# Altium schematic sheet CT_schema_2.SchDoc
size 283 x 147 mm
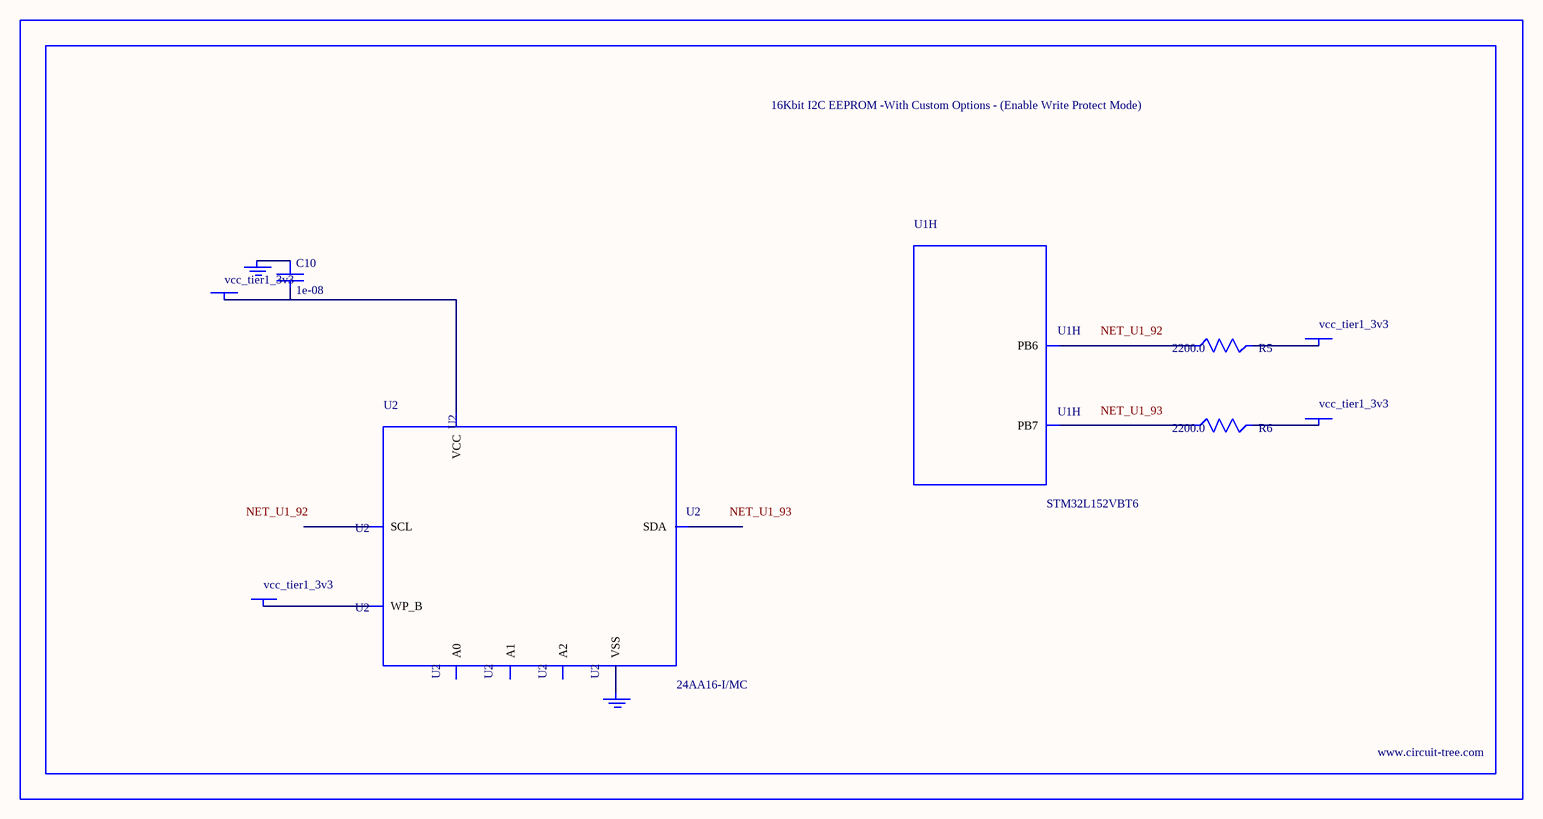
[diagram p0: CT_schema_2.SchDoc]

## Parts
BORDER1  (no value)
C10  1e-08  [C0402]
GND_INSTANCE_1_0  (no value)
GND_INSTANCE_1_1  (no value)
POWER_INSTANCE_1_0  vcc_tier1_3v3
POWER_INSTANCE_1_1  vcc_tier1_3v3
POWER_INSTANCE_1_2  vcc_tier1_3v3
POWER_INSTANCE_1_3  vcc_tier1_3v3
R5  2200.0  [R0603]
R6  2200.0  [R0603]
U1  STM32L152VBT6  [LQFP100]  (part H of 8)
U2  24AA16-I/MC  [TDFN-8/6MM]

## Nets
NetC10_1: C10.1 GND_INSTANCE_1_0.0(GND)
NetC10_2: C10.2 POWER_INSTANCE_1_1.0(PWR) U2.8(VCC)
NetGND_INSTANCE_1_1_0: GND_INSTANCE_1_1.0(GND) U2.4(VSS)
NetPOWER_INSTANCE_1_0_0: POWER_INSTANCE_1_0.0(PWR) U2.7(WP_B)
NetPOWER_INSTANCE_1_2_0: POWER_INSTANCE_1_2.0(PWR) R5.2
NetPOWER_INSTANCE_1_3_0: POWER_INSTANCE_1_3.0(PWR) R6.2
NetR5_1: R5.1 U1.92(PB6)
NetR6_1: R6.1 U1.93(PB7)

Not connected (* = marked no-connect by the designer): U2 1(A0) 2(A1) 3(A2) 5(SDA) 6(SCL)

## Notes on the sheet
- Labels drawn without touching a wire or pin: NET_U1_92, NET_U1_93

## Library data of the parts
BORDER1 = BORDER_PAGE1
C10 = C0402C103K3RAC
GND_INSTANCE_1_0 GND_INSTANCE_1_1 = GND
POWER_INSTANCE_1_0-POWER_INSTANCE_1_3 = PWR
R5 R6 = RC0603JR-072K2L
